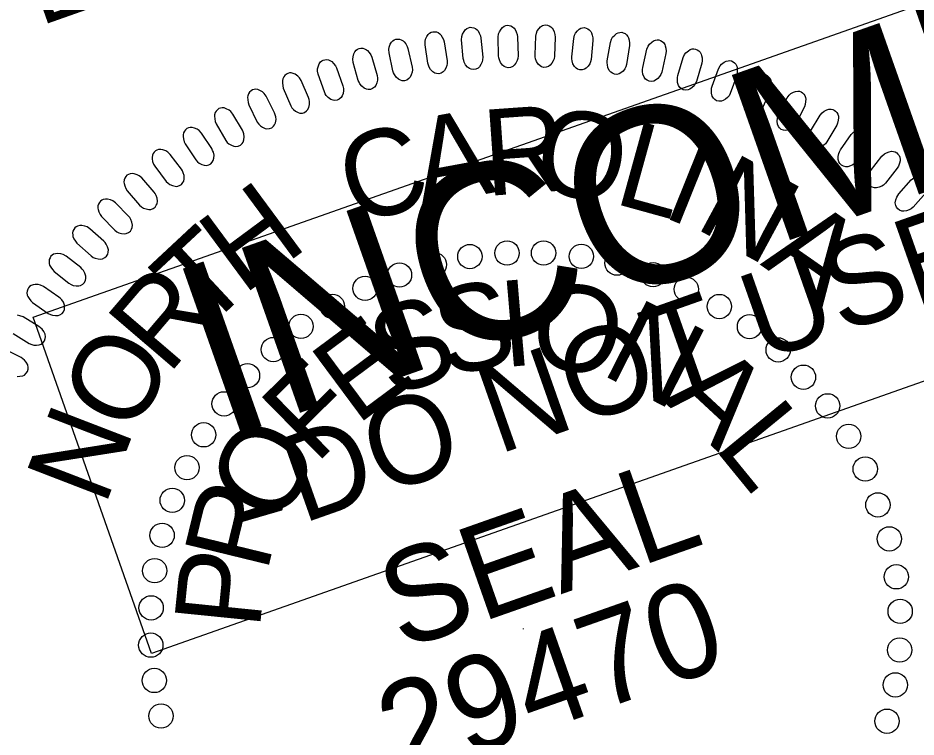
# Model space of a CAD drawing. Extents: x 473817 to 475769, y 501102 to 502694.
# Drawn here: x 475255.4 to 475314.6, y 502515.6 to 502563 of the extents above; entities that cross this region are included whole.
import ezdxf

# ---------------------------------------------------------------- set-up
doc = ezdxf.new("R2010")
doc.units = 0
for name, color, linetype in [('Sheet PE Seal Cell', 7, 'Continuous'), ('Sheet Plan CELL', 7, 'Continuous'), ('Sheet Sticker Incomplete CELL', 7, 'Continuous')]:
    doc.layers.add(name, color=color, linetype=linetype)

msp = doc.modelspace()

# ---------------------------------------------------------------- linework, layer by layer
at = {"layer": 'Sheet PE Seal Cell'}
msp.add_line((475288.665, 502522.782), (475288.681, 502522.738), dxfattribs=at)
for points in [[(475287.057, 502560.495), (475287.027, 502561.722), (475287.059, 502561.942), (475287.108, 502562.082), (475287.216, 502562.255), (475287.311, 502562.367), (475287.42, 502562.45), (475287.524, 502562.492), (475287.636, 502562.515), (475287.748, 502562.497), (475287.869, 502562.47), (475287.975, 502562.413), (475288.082, 502562.316), (475288.143, 502562.238), (475288.215, 502562.09), (475288.279, 502561.912), (475288.305, 502561.753), (475288.343, 502560.497), (475288.325, 502560.327), (475288.284, 502560.186), (475288.198, 502560.024), (475288.089, 502559.882), (475287.994, 502559.8), (475287.838, 502559.736), (475287.689, 502559.713), (475287.539, 502559.749), (475287.433, 502559.796), (475287.304, 502559.892), (475287.18, 502560.059), (475287.108, 502560.237), (475287.076, 502560.366)], [(475289.455, 502560.561), (475289.502, 502561.787), (475289.548, 502562.005), (475289.605, 502562.142), (475289.724, 502562.308), (475289.825, 502562.414), (475289.94, 502562.489), (475290.046, 502562.525), (475290.159, 502562.541), (475290.27, 502562.516), (475290.389, 502562.482), (475290.491, 502562.418), (475290.592, 502562.314), (475290.649, 502562.232), (475290.71, 502562.08), (475290.763, 502561.899), (475290.78, 502561.738), (475290.739, 502560.482), (475290.709, 502560.314), (475290.66, 502560.176), (475290.564, 502560.02), (475290.447, 502559.884), (475290.347, 502559.808), (475290.187, 502559.755), (475290.037, 502559.741), (475289.889, 502559.786), (475289.786, 502559.84), (475289.663, 502559.945), (475289.551, 502560.119), (475289.49, 502560.301), (475289.465, 502560.432)], [(475282.397, 502560.014), (475282.213, 502561.227), (475282.218, 502561.449), (475282.248, 502561.595), (475282.334, 502561.779), (475282.413, 502561.902), (475282.512, 502561.998), (475282.61, 502562.053), (475282.718, 502562.09), (475282.831, 502562.087), (475282.954, 502562.075), (475283.067, 502562.031), (475283.185, 502561.948), (475283.256, 502561.879), (475283.345, 502561.741), (475283.431, 502561.572), (475283.477, 502561.417), (475283.673, 502560.176), (475283.675, 502560.006), (475283.652, 502559.861), (475283.587, 502559.689), (475283.497, 502559.535), (475283.413, 502559.441), (475283.267, 502559.359), (475283.122, 502559.317), (475282.969, 502559.334), (475282.858, 502559.367), (475282.717, 502559.447), (475282.574, 502559.597), (475282.48, 502559.764), (475282.431, 502559.888)], [(475284.729, 502560.334), (475284.621, 502561.555), (475284.639, 502561.777), (475284.68, 502561.921), (475284.776, 502562.1), (475284.863, 502562.217), (475284.968, 502562.307), (475285.069, 502562.355), (475285.179, 502562.386), (475285.292, 502562.376), (475285.414, 502562.356), (475285.524, 502562.306), (475285.636, 502562.215), (475285.703, 502562.141), (475285.783, 502561.998), (475285.859, 502561.824), (475285.895, 502561.667), (475286.012, 502560.416), (475286.004, 502560.245), (475285.971, 502560.102), (475285.896, 502559.935), (475285.796, 502559.786), (475285.707, 502559.698), (475285.556, 502559.625), (475285.409, 502559.592), (475285.256, 502559.619), (475285.148, 502559.66), (475285.012, 502559.748), (475284.878, 502559.906), (475284.796, 502560.079), (475284.755, 502560.205)], [(475291.879, 502560.426), (475292.003, 502561.646), (475292.062, 502561.861), (475292.129, 502561.994), (475292.257, 502562.152), (475292.365, 502562.251), (475292.485, 502562.319), (475292.593, 502562.348), (475292.707, 502562.357), (475292.816, 502562.325), (475292.932, 502562.284), (475293.03, 502562.214), (475293.124, 502562.104), (475293.176, 502562.019), (475293.227, 502561.862), (475293.269, 502561.678), (475293.275, 502561.517), (475293.156, 502560.266), (475293.116, 502560.1), (475293.057, 502559.965), (475292.952, 502559.815), (475292.826, 502559.688), (475292.721, 502559.618), (475292.559, 502559.574), (475292.408, 502559.57), (475292.264, 502559.625), (475292.165, 502559.685), (475292.048, 502559.797), (475291.947, 502559.978), (475291.898, 502560.163), (475291.882, 502560.295)], [(475294.22, 502560.175), (475294.42, 502561.385), (475294.493, 502561.595), (475294.567, 502561.724), (475294.706, 502561.873), (475294.819, 502561.966), (475294.943, 502562.026), (475295.053, 502562.048), (475295.167, 502562.05), (475295.274, 502562.011), (475295.387, 502561.962), (475295.481, 502561.887), (475295.568, 502561.771), (475295.614, 502561.683), (475295.656, 502561.524), (475295.685, 502561.337), (475295.682, 502561.176), (475295.484, 502559.935), (475295.434, 502559.772), (475295.367, 502559.641), (475295.253, 502559.498), (475295.119, 502559.379), (475295.01, 502559.316), (475294.845, 502559.282), (475294.695, 502559.287), (475294.553, 502559.351), (475294.458, 502559.417), (475294.349, 502559.537), (475294.259, 502559.723), (475294.222, 502559.911), (475294.213, 502560.045)], [(475280.095, 502559.506), (475279.836, 502560.705), (475279.826, 502560.928), (475279.848, 502561.075), (475279.921, 502561.264), (475279.993, 502561.392), (475280.086, 502561.494), (475280.18, 502561.555), (475280.285, 502561.598), (475280.399, 502561.602), (475280.522, 502561.598), (475280.637, 502561.562), (475280.761, 502561.486), (475280.836, 502561.421), (475280.934, 502561.289), (475281.029, 502561.126), (475281.085, 502560.975), (475281.358, 502559.748), (475281.372, 502559.578), (475281.358, 502559.432), (475281.304, 502559.257), (475281.224, 502559.097), (475281.146, 502558.999), (475281.005, 502558.907), (475280.863, 502558.856), (475280.709, 502558.863), (475280.596, 502558.89), (475280.45, 502558.96), (475280.297, 502559.101), (475280.194, 502559.262), (475280.137, 502559.383)], [(475296.555, 502559.742), (475296.831, 502560.937), (475296.917, 502561.142), (475296.999, 502561.266), (475297.146, 502561.406), (475297.266, 502561.492), (475297.393, 502561.544), (475297.504, 502561.559), (475297.618, 502561.553), (475297.722, 502561.509), (475297.832, 502561.452), (475297.921, 502561.371), (475298, 502561.25), (475298.04, 502561.159), (475298.073, 502560.998), (475298.091, 502560.81), (475298.076, 502560.649), (475297.801, 502559.423), (475297.741, 502559.263), (475297.666, 502559.137), (475297.543, 502559.002), (475297.402, 502558.891), (475297.29, 502558.834), (475297.123, 502558.812), (475296.973, 502558.826), (475296.837, 502558.898), (475296.745, 502558.971), (475296.644, 502559.096), (475296.566, 502559.288), (475296.54, 502559.479), (475296.541, 502559.612)], [(475277.809, 502558.885), (475277.475, 502560.066), (475277.451, 502560.287), (475277.463, 502560.436), (475277.525, 502560.63), (475277.589, 502560.761), (475277.675, 502560.869), (475277.765, 502560.935), (475277.868, 502560.985), (475277.981, 502560.996), (475278.104, 502561), (475278.221, 502560.971), (475278.349, 502560.904), (475278.428, 502560.844), (475278.534, 502560.718), (475278.64, 502560.562), (475278.705, 502560.415), (475279.054, 502559.207), (475279.079, 502559.038), (475279.074, 502558.891), (475279.031, 502558.713), (475278.961, 502558.549), (475278.889, 502558.445), (475278.755, 502558.345), (475278.616, 502558.284), (475278.461, 502558.282), (475278.347, 502558.302), (475278.198, 502558.364), (475278.037, 502558.494), (475277.923, 502558.648), (475277.859, 502558.765)], [(475298.864, 502559.206), (475299.215, 502560.381), (475299.313, 502560.581), (475299.403, 502560.7), (475299.559, 502560.83), (475299.684, 502560.908), (475299.813, 502560.952), (475299.926, 502560.96), (475300.039, 502560.948), (475300.141, 502560.897), (475300.246, 502560.834), (475300.329, 502560.747), (475300.402, 502560.621), (475300.436, 502560.527), (475300.458, 502560.365), (475300.464, 502560.176), (475300.44, 502560.016), (475300.088, 502558.81), (475300.018, 502558.654), (475299.935, 502558.533), (475299.804, 502558.406), (475299.656, 502558.303), (475299.54, 502558.255), (475299.373, 502558.243), (475299.224, 502558.266), (475299.092, 502558.347), (475299.006, 502558.425), (475298.913, 502558.556), (475298.847, 502558.753), (475298.833, 502558.945), (475298.842, 502559.078)], [(475275.575, 502558.126), (475275.168, 502559.283), (475275.13, 502559.502), (475275.133, 502559.652), (475275.183, 502559.849), (475275.238, 502559.985), (475275.317, 502560.097), (475275.402, 502560.169), (475275.502, 502560.226), (475275.614, 502560.244), (475275.737, 502560.256), (475275.855, 502560.234), (475275.987, 502560.175), (475276.07, 502560.119), (475276.183, 502560), (475276.3, 502559.851), (475276.374, 502559.708), (475276.798, 502558.525), (475276.834, 502558.358), (475276.837, 502558.211), (475276.806, 502558.031), (475276.746, 502557.861), (475276.681, 502557.754), (475276.553, 502557.646), (475276.419, 502557.578), (475276.265, 502557.565), (475276.15, 502557.577), (475275.996, 502557.629), (475275.827, 502557.75), (475275.704, 502557.896), (475275.633, 502558.009)], [(475301.122, 502558.5), (475301.546, 502559.651), (475301.656, 502559.844), (475301.753, 502559.957), (475301.917, 502560.078), (475302.046, 502560.147), (475302.179, 502560.183), (475302.291, 502560.185), (475302.404, 502560.164), (475302.502, 502560.108), (475302.604, 502560.038), (475302.681, 502559.946), (475302.745, 502559.816), (475302.774, 502559.721), (475302.785, 502559.557), (475302.779, 502559.368), (475302.746, 502559.21), (475302.319, 502558.028), (475302.239, 502557.877), (475302.148, 502557.761), (475302.009, 502557.643), (475301.856, 502557.55), (475301.737, 502557.508), (475301.569, 502557.506), (475301.422, 502557.54), (475301.295, 502557.629), (475301.214, 502557.712), (475301.13, 502557.849), (475301.076, 502558.049), (475301.075, 502558.242), (475301.092, 502558.373)], [(475274.527, 502557.747), (475274.047, 502558.876), (475273.927, 502559.063), (475273.824, 502559.171), (475273.655, 502559.284), (475273.523, 502559.347), (475273.388, 502559.376), (475273.276, 502559.372), (475273.165, 502559.346), (475273.07, 502559.284), (475272.972, 502559.21), (475272.898, 502559.114), (475272.841, 502558.981), (475272.818, 502558.885), (475272.814, 502558.72), (475272.829, 502558.532), (475272.871, 502558.377), (475273.355, 502557.217), (475273.442, 502557.07), (475273.538, 502556.959), (475273.682, 502556.846), (475273.84, 502556.762), (475273.961, 502556.726), (475274.129, 502556.733), (475274.274, 502556.773), (475274.396, 502556.868), (475274.473, 502556.955), (475274.551, 502557.097), (475274.595, 502557.299), (475274.586, 502557.491), (475274.564, 502557.622)], [(475303.296, 502557.661), (475303.792, 502558.784), (475303.914, 502558.97), (475304.018, 502559.076), (475304.189, 502559.186), (475304.323, 502559.247), (475304.457, 502559.275), (475304.569, 502559.27), (475304.68, 502559.242), (475304.774, 502559.179), (475304.871, 502559.103), (475304.943, 502559.007), (475304.999, 502558.873), (475305.022, 502558.775), (475305.022, 502558.611), (475305.005, 502558.423), (475304.961, 502558.268), (475304.461, 502557.115), (475304.372, 502556.97), (475304.274, 502556.86), (475304.128, 502556.75), (475303.97, 502556.667), (475303.848, 502556.634), (475303.68, 502556.642), (475303.535, 502556.684), (475303.415, 502556.781), (475303.339, 502556.869), (475303.263, 502557.011), (475303.222, 502557.215), (475303.233, 502557.406), (475303.258, 502557.537)], [(475272.294, 502556.745), (475271.745, 502557.841), (475271.614, 502558.021), (475271.504, 502558.122), (475271.328, 502558.224), (475271.192, 502558.278), (475271.056, 502558.299), (475270.944, 502558.288), (475270.835, 502558.256), (475270.744, 502558.188), (475270.65, 502558.108), (475270.584, 502558.007), (475270.535, 502557.871), (475270.517, 502557.773), (475270.524, 502557.609), (475270.551, 502557.422), (475270.602, 502557.269), (475271.158, 502556.143), (475271.254, 502556.001), (475271.357, 502555.896), (475271.508, 502555.793), (475271.671, 502555.719), (475271.794, 502555.691), (475271.961, 502555.707), (475272.104, 502555.757), (475272.219, 502555.859), (475272.291, 502555.951), (475272.36, 502556.097), (475272.391, 502556.302), (475272.37, 502556.493), (475272.339, 502556.622)], [(475305.505, 502556.644), (475306.069, 502557.733), (475306.203, 502557.911), (475306.314, 502558.011), (475306.491, 502558.11), (475306.628, 502558.163), (475306.764, 502558.182), (475306.876, 502558.169), (475306.985, 502558.136), (475307.075, 502558.066), (475307.167, 502557.984), (475307.233, 502557.883), (475307.28, 502557.747), (475307.296, 502557.648), (475307.287, 502557.484), (475307.258, 502557.298), (475307.204, 502557.145), (475306.632, 502556.026), (475306.534, 502555.886), (475306.43, 502555.783), (475306.278, 502555.683), (475306.114, 502555.61), (475305.99, 502555.584), (475305.824, 502555.603), (475305.681, 502555.654), (475305.567, 502555.758), (475305.497, 502555.85), (475305.43, 502555.998), (475305.402, 502556.203), (475305.425, 502556.394), (475305.458, 502556.523)], [(475270.171, 502555.606), (475269.555, 502556.665), (475269.412, 502556.837), (475269.296, 502556.931), (475269.114, 502557.021), (475268.975, 502557.067), (475268.838, 502557.08), (475268.727, 502557.061), (475268.62, 502557.023), (475268.533, 502556.949), (475268.445, 502556.863), (475268.385, 502556.759), (475268.344, 502556.619), (475268.333, 502556.52), (475268.35, 502556.357), (475268.388, 502556.172), (475268.449, 502556.023), (475269.075, 502554.933), (475269.18, 502554.798), (475269.289, 502554.7), (475269.447, 502554.607), (475269.614, 502554.543), (475269.738, 502554.523), (475269.904, 502554.55), (475270.043, 502554.608), (475270.152, 502554.718), (475270.217, 502554.814), (475270.277, 502554.963), (475270.295, 502555.17), (475270.263, 502555.359), (475270.223, 502555.486)], [(475307.605, 502555.533), (475308.237, 502556.585), (475308.383, 502556.754), (475308.499, 502556.847), (475308.682, 502556.934), (475308.823, 502556.978), (475308.96, 502556.989), (475309.07, 502556.969), (475309.177, 502556.929), (475309.262, 502556.854), (475309.349, 502556.766), (475309.409, 502556.661), (475309.446, 502556.522), (475309.457, 502556.423), (475309.437, 502556.259), (475309.396, 502556.075), (475309.333, 502555.927), (475308.692, 502554.846), (475308.586, 502554.712), (475308.475, 502554.615), (475308.316, 502554.525), (475308.148, 502554.463), (475308.024, 502554.444), (475307.858, 502554.474), (475307.72, 502554.534), (475307.613, 502554.645), (475307.549, 502554.742), (475307.491, 502554.893), (475307.476, 502555.099), (475307.511, 502555.288), (475307.552, 502555.415)], [(475268.154, 502554.394), (475267.472, 502555.413), (475267.319, 502555.575), (475267.197, 502555.662), (475267.01, 502555.74), (475266.868, 502555.777), (475266.731, 502555.781), (475266.621, 502555.756), (475266.517, 502555.71), (475266.435, 502555.632), (475266.352, 502555.54), (475266.299, 502555.432), (475266.267, 502555.291), (475266.262, 502555.192), (475266.289, 502555.029), (475266.339, 502554.847), (475266.409, 502554.702), (475267.102, 502553.654), (475267.215, 502553.525), (475267.33, 502553.435), (475267.494, 502553.352), (475267.664, 502553.298), (475267.789, 502553.286), (475267.954, 502553.323), (475268.089, 502553.39), (475268.191, 502553.506), (475268.25, 502553.606), (475268.3, 502553.76), (475268.305, 502553.967), (475268.261, 502554.154), (475268.214, 502554.277)], [(475309.588, 502554.3), (475310.285, 502555.31), (475310.441, 502555.469), (475310.563, 502555.555), (475310.752, 502555.631), (475310.894, 502555.666), (475311.031, 502555.668), (475311.14, 502555.641), (475311.244, 502555.594), (475311.325, 502555.514), (475311.406, 502555.421), (475311.459, 502555.313), (475311.488, 502555.171), (475311.492, 502555.071), (475311.462, 502554.91), (475311.41, 502554.728), (475311.338, 502554.584), (475310.63, 502553.546), (475310.516, 502553.419), (475310.399, 502553.329), (475310.235, 502553.249), (475310.063, 502553.198), (475309.938, 502553.187), (475309.775, 502553.227), (475309.64, 502553.295), (475309.54, 502553.413), (475309.482, 502553.514), (475309.434, 502553.668), (475309.432, 502553.875), (475309.478, 502554.061), (475309.528, 502554.185)], [(475266.16, 502553.033), (475265.414, 502554.007), (475265.252, 502554.159), (475265.125, 502554.238), (475264.934, 502554.304), (475264.789, 502554.333), (475264.652, 502554.328), (475264.544, 502554.296), (475264.443, 502554.244), (475264.366, 502554.16), (475264.29, 502554.063), (475264.243, 502553.953), (475264.22, 502553.81), (475264.221, 502553.71), (475264.258, 502553.55), (475264.32, 502553.371), (475264.399, 502553.23), (475265.156, 502552.228), (475265.277, 502552.107), (475265.398, 502552.023), (475265.566, 502551.951), (475265.74, 502551.908), (475265.865, 502551.904), (475266.027, 502551.952), (475266.157, 502552.027), (475266.252, 502552.149), (475266.305, 502552.253), (475266.345, 502552.409), (475266.337, 502552.616), (475266.282, 502552.799), (475266.227, 502552.921)], [(475311.557, 502552.931), (475312.315, 502553.895), (475312.481, 502554.044), (475312.608, 502554.122), (475312.801, 502554.186), (475312.945, 502554.212), (475313.082, 502554.205), (475313.189, 502554.172), (475313.29, 502554.118), (475313.366, 502554.033), (475313.441, 502553.936), (475313.486, 502553.824), (475313.507, 502553.681), (475313.505, 502553.581), (475313.465, 502553.421), (475313.401, 502553.244), (475313.32, 502553.105), (475312.549, 502552.112), (475312.426, 502551.993), (475312.305, 502551.911), (475312.135, 502551.841), (475311.961, 502551.801), (475311.835, 502551.798), (475311.675, 502551.848), (475311.545, 502551.925), (475311.453, 502552.049), (475311.401, 502552.152), (475311.363, 502552.31), (475311.373, 502552.517), (475311.432, 502552.7), (475311.488, 502552.82)], [(475264.356, 502551.531), (475263.551, 502552.457), (475263.378, 502552.598), (475263.248, 502552.669), (475263.052, 502552.723), (475262.906, 502552.742), (475262.77, 502552.729), (475262.664, 502552.69), (475262.567, 502552.631), (475262.495, 502552.543), (475262.424, 502552.442), (475262.385, 502552.328), (475262.371, 502552.184), (475262.378, 502552.085), (475262.426, 502551.928), (475262.499, 502551.753), (475262.586, 502551.618), (475263.405, 502550.665), (475263.533, 502550.552), (475263.659, 502550.476), (475263.831, 502550.414), (475264.007, 502550.382), (475264.133, 502550.385), (475264.291, 502550.443), (475264.417, 502550.527), (475264.503, 502550.655), (475264.549, 502550.761), (475264.58, 502550.92), (475264.559, 502551.126), (475264.492, 502551.306), (475264.429, 502551.423)], [(475262.669, 502549.947), (475261.808, 502550.82), (475261.627, 502550.95), (475261.491, 502551.013), (475261.293, 502551.056), (475261.146, 502551.065), (475261.011, 502551.043), (475260.908, 502550.998), (475260.814, 502550.933), (475260.748, 502550.84), (475260.684, 502550.735), (475260.652, 502550.619), (475260.647, 502550.474), (475260.661, 502550.376), (475260.718, 502550.222), (475260.801, 502550.052), (475260.897, 502549.923), (475261.774, 502549.023), (475261.91, 502548.918), (475262.04, 502548.85), (475262.215, 502548.8), (475262.394, 502548.779), (475262.518, 502548.79), (475262.672, 502548.858), (475262.793, 502548.949), (475262.871, 502549.082), (475262.911, 502549.191), (475262.931, 502549.351), (475262.898, 502549.556), (475262.819, 502549.731), (475262.749, 502549.844)], [(475261.042, 502548.298), (475260.127, 502549.116), (475259.938, 502549.234), (475259.8, 502549.288), (475259.599, 502549.318), (475259.452, 502549.318), (475259.318, 502549.288), (475259.219, 502549.236), (475259.128, 502549.166), (475259.069, 502549.07), (475259.011, 502548.96), (475258.986, 502548.842), (475258.991, 502548.698), (475259.01, 502548.6), (475259.077, 502548.45), (475259.171, 502548.285), (475259.275, 502548.163), (475260.207, 502547.32), (475260.348, 502547.223), (475260.482, 502547.164), (475260.66, 502547.124), (475260.84, 502547.115), (475260.964, 502547.134), (475261.114, 502547.211), (475261.228, 502547.309), (475261.298, 502547.447), (475261.33, 502547.559), (475261.341, 502547.72), (475261.294, 502547.922), (475261.205, 502548.092), (475261.128, 502548.2)], [(475259.519, 502546.55), (475258.555, 502547.309), (475258.359, 502547.415), (475258.217, 502547.46), (475258.015, 502547.478), (475257.868, 502547.468), (475257.737, 502547.43), (475257.64, 502547.372), (475257.555, 502547.296), (475257.501, 502547.196), (475257.451, 502547.083), (475257.433, 502546.964), (475257.447, 502546.82), (475257.473, 502546.724), (475257.548, 502546.578), (475257.653, 502546.421), (475257.764, 502546.304), (475258.747, 502545.521), (475258.894, 502545.434), (475259.032, 502545.383), (475259.213, 502545.355), (475259.392, 502545.357), (475259.514, 502545.383), (475259.659, 502545.47), (475259.767, 502545.575), (475259.828, 502545.717), (475259.853, 502545.831), (475259.854, 502545.992), (475259.794, 502546.191), (475259.694, 502546.355), (475259.612, 502546.458)], [(475258.083, 502544.607), (475257.072, 502545.304), (475256.871, 502545.398), (475256.726, 502545.434), (475256.523, 502545.438), (475256.377, 502545.42), (475256.248, 502545.373), (475256.155, 502545.31), (475256.076, 502545.228), (475256.028, 502545.125), (475255.985, 502545.01), (475255.975, 502544.89), (475255.998, 502544.747), (475256.029, 502544.652), (475256.115, 502544.512), (475256.228, 502544.361), (475256.347, 502544.252), (475257.377, 502543.532), (475257.53, 502543.454), (475257.67, 502543.411), (475257.852, 502543.395), (475258.03, 502543.408), (475258.152, 502543.442), (475258.29, 502543.538), (475258.391, 502543.65), (475258.443, 502543.795), (475258.461, 502543.91), (475258.452, 502544.071), (475258.38, 502544.266), (475258.27, 502544.423), (475258.18, 502544.522)]]:
    msp.add_lwpolyline(points, close=True, dxfattribs=at)
for points in [[(475315.198, 502551.48), (475314.366, 502550.538), (475314.236, 502550.426), (475314.11, 502550.352), (475313.937, 502550.293), (475313.761, 502550.264), (475313.634, 502550.269), (475313.478, 502550.329), (475313.353, 502550.414), (475313.268, 502550.543), (475313.223, 502550.65), (475313.195, 502550.809), (475313.219, 502551.015), (475313.288, 502551.194), (475313.353, 502551.311), (475313.428, 502551.417), (475314.245, 502552.331), (475314.42, 502552.47), (475314.551, 502552.54), (475314.748, 502552.592)], [(475255.061, 502542.207), (475256.134, 502541.554), (475256.291, 502541.486), (475256.434, 502541.453), (475256.617, 502541.447), (475256.794, 502541.472), (475256.913, 502541.514), (475257.045, 502541.618), (475257.139, 502541.736), (475257.181, 502541.884), (475257.193, 502541.999), (475257.173, 502542.16), (475257.089, 502542.349), (475256.97, 502542.499), (475256.874, 502542.592), (475256.771, 502542.672), (475255.719, 502543.304), (475255.512, 502543.384), (475255.365, 502543.412)], [(475255.337, 502539.389), (475255.52, 502539.395), (475255.696, 502539.43), (475255.811, 502539.479), (475255.937, 502539.591), (475256.023, 502539.715), (475256.056, 502539.866), (475256.06, 502539.982), (475256.03, 502540.141), (475255.935, 502540.325), (475255.806, 502540.467), (475255.705, 502540.553), (475255.597, 502540.626), (475254.508, 502541.191)]]:
    msp.add_lwpolyline(points, dxfattribs=at)
for centre in [(475287.614, 502547.51), (475290.019, 502547.512), (475285.162, 502547.28), (475292.503, 502547.29), (475294.853, 502546.85), (475282.816, 502546.749), (475280.524, 502546.068), (475297.234, 502546.084), (475278.259, 502545.186), (475299.429, 502545.125), (475276.101, 502544.004), (475301.601, 502543.99), (475274.033, 502542.684), (475303.589, 502542.662), (475272.208, 502541.154), (475305.478, 502541.132), (475270.51, 502539.431), (475307.143, 502539.334), (475268.968, 502537.578), (475308.737, 502537.446), (475267.618, 502535.54), (475310.119, 502535.44), (475266.521, 502533.38), (475311.213, 502533.292), (475265.551, 502531.222), (475312.047, 502530.924), (475264.885, 502528.918), (475312.805, 502528.685), (475264.396, 502526.591), (475313.263, 502526.186), (475264.161, 502524.143), (475313.516, 502523.91), (475264.14, 502521.686), (475313.484, 502521.364), (475264.368, 502519.359), (475313.196, 502519.067), (475264.811, 502517.023), (475312.645, 502516.676)]:
    msp.add_circle(centre, 0.801, dxfattribs=at)
at = {"layer": 'Sheet Sticker Incomplete CELL'}
msp.add_lwpolyline([(475264.194, 502521.136), (475256.379, 502543.298), (475395.013, 502592.182), (475402.828, 502570.019)], close=True, dxfattribs=at)

# ---------------------------------------------------------------- texts
at = {"layer": 'Sheet PE Seal Cell'}
for s, height, rotation, p in [('R', 5.669, 4.03196, (475286.219, 502551.267)), ('A', 5.669, 10.52131, (475281.987, 502550.617)), ('O', 5.669, 351.05324, (475289.223, 502551.633)), ('L', 5.669, 344.56389, (475294.528, 502550.82)), ('C', 5.669, 17.01067, (475277.603, 502549.292)), ('I', 5.669, 338.07453, (475297.684, 502549.968)), ('N', 5.669, 331.58517, (475299.859, 502549.228)), ('H', 5.669, 36.47874, (475270.208, 502544.688)), ('A', 5.669, 325.09581, (475304.247, 502546.767)), ('T', 5.669, 42.96809, (475267.679, 502542.301)), ('R', 5.669, 49.45745, (475265.28, 502539.42)), ('S', 5.669, 12.77222, (475283.579, 502539.32)), ('I', 5.669, 4.83243, (475287.373, 502539.988)), ('O', 5.669, 348.95283, (475288.848, 502540.326)), ('S', 5.669, 20.71202, (475279.971, 502537.941)), ('N', 5.669, 333.07324, (475293.681, 502539.587)), ('E', 5.669, 36.59162, (475277.681, 502536.115)), ('O', 5.669, 62.43617, (475263.009, 502535.408)), ('F', 5.669, 44.53141, (475274.995, 502533.537)), ('A', 5.669, 317.19364, (475297.852, 502537.791)), ('L', 5.669, 309.25385, (475301.184, 502534.73)), ('N', 5.669, 68.92552, (475261.102, 502530.754)), ('O', 5.669, 60.41101, (475272.552, 502529.348)), ('SEAL', 6.2363, 19.40435, (475280.651, 502521.327)), ('R', 5.669, 76.29061, (475271.782, 502526.376)), ('P', 5.669, 84.2304, (475271.31, 502522.645)), ('29470', 6.2363, 19.40435, (475280.535, 502512.72))]:
    msp.add_text(s, height=height, rotation=rotation, dxfattribs=at).set_placement(p)
at = {"layer": 'Sheet Plan CELL'}
msp.add_text('ENGINEER', height=5.0001, rotation=19.42299, dxfattribs=at).set_placement((475256.847, 502562.457))
at = {"layer": 'Sheet Sticker Incomplete CELL'}
for s, height, p in [('INCOMPLETE PLANS', 11.52, (475268.744, 502535.146)), ('DO NOT USE FOR R/W ACQUISITION', 5.76, (475274.12, 502529.672))]:
    msp.add_text(s, height=height, rotation=19.42299, dxfattribs=at).set_placement(p)

doc.saveas('drawing.dxf')
